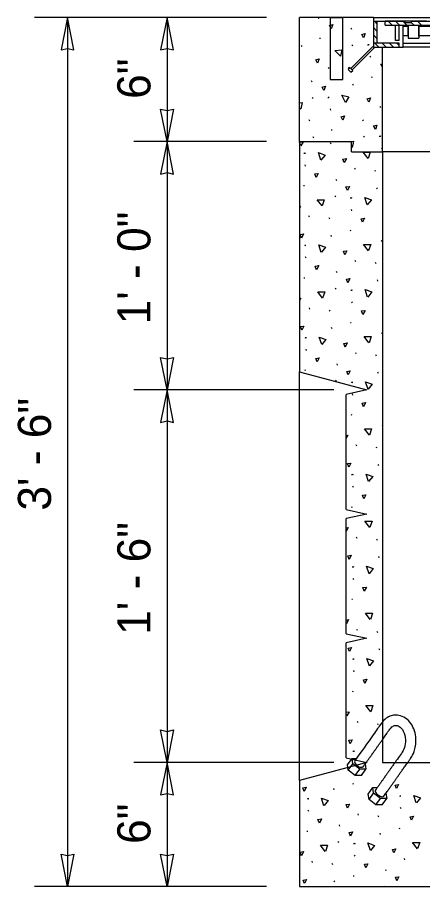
# Model space of a CAD drawing. Extents: x 99862 to 103151, y 100000 to 105076.
# Drawn here: x 100850.3 to 101045.9, y 100268.1 to 100688.1 of the extents above; entities that cross this region are included whole.
import ezdxf

# ---------------------------------------------------------------- set-up
doc = ezdxf.new("R2010")
doc.units = 0
for name, color, linetype in [('Level 15', 7, 'Continuous'), ('Level 19', 7, 'Continuous'), ('Level 2', 7, 'Continuous'), ('Level 20', 7, 'Continuous'), ('Level 3', 7, 'Continuous'), ('Level 4', 7, 'Continuous'), ('Level 5', 7, 'Continuous'), ('Level 50', 7, 'Continuous'), ('Level 7', 7, 'Continuous')]:
    doc.layers.add(name, color=color, linetype=linetype)

msp = doc.modelspace()

# ---------------------------------------------------------------- linework, layer by layer
at = {"layer": 'Level 15'}
for p, q in [((100970.51, 100688.11), (100858.51, 100688.11)), ((100874.51, 100688.11), (100874.51, 100268.11)), ((100922.51, 100688.11), (100922.51, 100628.11)), ((100970.51, 100628.11), (100906.51, 100628.11)), ((100922.51, 100628.11), (100922.51, 100508.11)), ((101003.01, 100508.11), (100906.51, 100508.11)), ((100922.51, 100508.11), (100922.51, 100328.11)), ((101003.01, 100328.11), (100906.51, 100328.11)), ((100922.51, 100328.11), (100922.51, 100268.11)), ((100970.51, 100268.11), (100858.51, 100268.11))]:
    msp.add_line(p, q, dxfattribs=at)
for points in [[(100874.51, 100688.11), (100871.43, 100672.38), (100874.51, 100673.11), (100877.59, 100672.38)], [(100922.51, 100688.11), (100919.43, 100672.38), (100922.51, 100673.11), (100925.59, 100672.38)], [(100922.51, 100628.11), (100919.43, 100643.83), (100922.51, 100643.1), (100925.59, 100643.83)], [(100922.51, 100628.11), (100919.43, 100612.38), (100922.51, 100613.11), (100925.59, 100612.38)], [(100922.51, 100508.11), (100919.43, 100523.83), (100922.51, 100523.1), (100925.59, 100523.83)], [(100922.51, 100508.11), (100919.43, 100492.38), (100922.51, 100493.11), (100925.59, 100492.38)], [(100922.51, 100328.11), (100919.43, 100343.83), (100922.51, 100343.1), (100925.59, 100343.83)], [(100922.51, 100328.11), (100919.43, 100312.38), (100922.51, 100313.11), (100925.59, 100312.38)], [(100874.51, 100268.11), (100871.43, 100283.83), (100874.51, 100283.1), (100877.59, 100283.83)], [(100922.51, 100268.11), (100919.43, 100283.83), (100922.51, 100283.1), (100925.59, 100283.83)]]:
    msp.add_lwpolyline(points, close=True, dxfattribs=at)
at = {"layer": 'Level 19'}
for p, q in [((100996.03, 100687.5), (100995.71, 100688.07)), ((101011.79, 100682.3), (101011.47, 100682.87)), ((100987.75, 100673.97), (100987.43, 100674.54)), ((100996.17, 100678.05), (100996.65, 100678.03)), ((101011.73, 100674.9), (101012.25, 100674.59)), ((101019.3, 100674.89), (101019.78, 100674.86)), ((101019.58, 100675.01), (101020.06, 100674.98)), ((101020.87, 100668.78), (101020.56, 100669.35)), ((101000.86, 100663.26), (101000.54, 100663.83)), ((101010.68, 100663.45), (101010.36, 100664.02)), ((100992.59, 100656.82), (100992.27, 100657.39)), ((101021.01, 100659.33), (101021.49, 100659.3)), ((101012.6, 100655.25), (101012.28, 100655.82)), ((100992.53, 100649.42), (100993.05, 100649.11)), ((101000.1, 100649.41), (101000.58, 100649.38)), ((101000.38, 100649.53), (101000.86, 100649.5)), ((101025.71, 100644.54), (101025.39, 100645.11)), ((101001.67, 100643.3), (101001.36, 100643.87)), ((100991.48, 100637.97), (100991.16, 100638.54)), ((101017.43, 100638.09), (101017.12, 100638.67)), ((101001.81, 100633.85), (101002.29, 100633.83)), ((100993.4, 100629.77), (100993.08, 100630.34)), ((101017.37, 100630.7), (101017.89, 100630.39)), ((101024.94, 100630.68), (101025.42, 100630.66)), ((101025.23, 100630.81), (101025.7, 100630.78)), ((101001.73, 100626.82), (101001.49, 100627.43)), ((101026.51, 100624.59), (101026.2, 100625.15)), ((100988.61, 100622.55), (100989.08, 100622.46)), ((100988.91, 100622.63), (100989.38, 100622.55)), ((100989.43, 100616.29), (100989.19, 100616.9)), ((101013.44, 100614.59), (101013.19, 100615.2)), ((101023.21, 100613.59), (101022.96, 100614.19)), ((100988.42, 100606.9), (100988.89, 100606.82)), ((101004.44, 100609.21), (101004.2, 100609.81)), ((101024.11, 100605.21), (101023.87, 100605.82)), ((101003.48, 100601.87), (101003.96, 100601.5)), ((101010.99, 100600.94), (101011.46, 100600.85)), ((101011.29, 100601.02), (101011.76, 100600.94)), ((101011.81, 100594.68), (101011.57, 100595.29)), ((100991.28, 100591.64), (100991.03, 100592.25)), ((101001.04, 100590.64), (101000.8, 100591.24)), ((101001.95, 100582.26), (101001.7, 100582.87)), ((101010.8, 100585.29), (101011.27, 100585.2)), ((100988.83, 100577.99), (100989.3, 100577.9)), ((100989.12, 100578.07), (100989.6, 100577.99)), ((101025.86, 100580.26), (101026.34, 100579.89)), ((100989.65, 100571.73), (100989.41, 100572.34)), ((101013.66, 100570.03), (101013.41, 100570.64)), ((101023.42, 100569.02), (101023.18, 100569.63)), ((101004.66, 100564.65), (101004.41, 100565.25)), ((100988.64, 100562.34), (100989.11, 100562.25)), ((101024.33, 100560.65), (101024.08, 100561.26)), ((101003.7, 100557.31), (101004.17, 100556.94)), ((101011.5, 100556.46), (101011.98, 100556.38)), ((101011.21, 100556.38), (101011.68, 100556.29)), ((101012.03, 100550.12), (101011.78, 100550.73)), ((100991.49, 100547.08), (100991.25, 100547.69)), ((101001.26, 100546.08), (101001.02, 100546.68)), ((101011.02, 100540.73), (101011.49, 100540.64)), ((101002.17, 100537.7), (101001.92, 100538.31)), ((101026.08, 100535.7), (101026.51, 100535.36)), ((100989.05, 100533.43), (100989.52, 100533.34)), ((100989.34, 100533.51), (100989.81, 100533.43)), ((100989.87, 100527.17), (100989.62, 100527.78)), ((101013.87, 100525.47), (101013.63, 100526.08)), ((101023.64, 100524.46), (101023.4, 100525.07)), ((101004.88, 100520.09), (101004.63, 100520.69)), ((100988.86, 100517.78), (100989.33, 100517.69)), ((101024.55, 100516.09), (101024.3, 100516.7)), ((101003.92, 100512.75), (101004.39, 100512.38)), ((101011.43, 100511.82), (101011.9, 100511.73)), ((101011.72, 100511.9), (101012.19, 100511.82)), ((101012.25, 100505.56), (101012, 100506.17)), ((101011.23, 100496.17), (101011.71, 100496.08)), ((101026.29, 100491.14), (101026.51, 100490.97)), ((101014.09, 100480.91), (101013.85, 100481.52)), ((101023.86, 100479.9), (101023.61, 100480.51)), ((101024.76, 100471.53), (101024.52, 100472.14)), ((101011.64, 100467.25), (101012.12, 100467.17)), ((101011.94, 100467.34), (101012.41, 100467.25)), ((101012.47, 100461), (101012.22, 100461.61)), ((101011.45, 100451.61), (101011.93, 100451.52)), ((101014.31, 100436.35), (101014.06, 100436.96)), ((101024.08, 100435.34), (101023.83, 100435.95)), ((101024.98, 100426.97), (101024.74, 100427.58)), ((101011.86, 100422.69), (101012.34, 100422.61)), ((101012.16, 100422.78), (101012.63, 100422.69)), ((101012.68, 100416.44), (101012.44, 100417.05)), ((101011.67, 100407.05), (101012.14, 100406.96)), ((101014.53, 100391.79), (101014.28, 100392.4)), ((101024.29, 100390.78), (101024.05, 100391.39)), ((101025.2, 100382.41), (101024.95, 100383.02)), ((101012.08, 100378.13), (101012.55, 100378.05)), ((101012.37, 100378.22), (101012.85, 100378.13)), ((101012.9, 100371.88), (101012.66, 100372.48)), ((101011.89, 100362.49), (101012.36, 100362.4)), ((101014.74, 100347.23), (101014.5, 100347.84)), ((101024.51, 100346.22), (101024.27, 100346.83)), ((101012.3, 100333.57), (101012.77, 100333.49)), ((101012.59, 100333.66), (101013.06, 100333.57)), ((101012.11, 100317.92), (101012.58, 100317.84)), ((101003.26, 100314.9), (101003.01, 100315.51)), ((100990.14, 100310.62), (100990.61, 100310.54)), ((100990.43, 100310.71), (100990.9, 100310.62)), ((101034.68, 100311.96), (101035.15, 100311.87)), ((101034.97, 100312.05), (101035.44, 100311.96)), ((100990.96, 100304.37), (100990.71, 100304.97)), ((101035.5, 100305.7), (101035.25, 100306.31)), ((101014.96, 100302.67), (101014.72, 100303.27)), ((101024.73, 100301.66), (101024.48, 100302.27)), ((101005.97, 100297.28), (101005.72, 100297.89)), ((101034.49, 100296.31), (101034.96, 100296.23)), ((100989.94, 100294.98), (100990.42, 100294.89)), ((101025.64, 100293.29), (101025.39, 100293.89)), ((101005, 100289.95), (101005.48, 100289.58)), ((101012.52, 100289.01), (101012.99, 100288.93)), ((101012.81, 100289.1), (101013.28, 100289.01)), ((100992.8, 100279.72), (100992.55, 100280.33)), ((101002.57, 100278.71), (101002.32, 100279.32)), ((101013.34, 100282.75), (101013.09, 100283.36)), ((101037.34, 100281.05), (101037.1, 100281.66)), ((101028.35, 100275.67), (101028.1, 100276.28)), ((101003.47, 100270.34), (101003.23, 100270.94)), ((101012.32, 100273.36), (101012.8, 100273.28)), ((101027.38, 100268.33), (101027.68, 100268.11))]:
    msp.add_line(p, q, dxfattribs=at)
for points in [[(101001.76, 100682.6), (101000.91, 100684.24), (101002.51, 100684.7), (101001.76, 100682.6)], [(101017.45, 100678.19), (101016.6, 100679.83), (101018.2, 100680.3), (101017.45, 100678.19)], [(101006.29, 100669.32), (101003.57, 100672.03), (101006.97, 100672.45), (101006.31, 100669.38)], [(101026.51, 100671.42), (101026.36, 100671.83), (101026.51, 100671.85)], [(100995.15, 100665.91), (100994.3, 100667.55), (100995.9, 100668.02), (100995.15, 100665.91)], [(101026.51, 100664.06), (101025.76, 100665.52), (101026.51, 100665.73)], [(100998.25, 100652.72), (100997.4, 100654.36), (100999, 100654.82), (100998.25, 100652.72)], [(101008.62, 100646.99), (101006.99, 100650.47), (101010.33, 100649.7), (101008.66, 100647.04)], [(101019.99, 100647.19), (101019.14, 100648.83), (101020.74, 100649.29), (101019.99, 100647.19)], [(100986.51, 100646.81), (100987.77, 100646.97), (100987.11, 100643.9)], [(100987.09, 100643.84), (100986.51, 100644.41)], [(101007.4, 100638.4), (101006.56, 100640.04), (101008.16, 100640.5), (101007.4, 100638.4)], [(101023.1, 100633.99), (101022.25, 100635.63), (101023.85, 100636.09), (101023.1, 100633.99)], [(100987.19, 100626.06), (100986.54, 100627.79), (100988.19, 100628.05), (100987.19, 100626.06)], [(101011.48, 100628.11), (101012.61, 100628.25), (101011.95, 100625.18)], [(101011.93, 100625.11), (101011.51, 100625.54)], [(100996.78, 100619.11), (100995.59, 100622.76), (100998.81, 100621.59), (100996.83, 100619.15)], [(101008.09, 100617.92), (101007.45, 100619.66), (101009.09, 100619.92), (101008.09, 100617.92)], [(101019.56, 100619.94), (101017.19, 100622.97), (101020.62, 100622.97), (101019.59, 100620)], [(100994.52, 100610.73), (100993.88, 100612.46), (100995.52, 100612.72), (100994.52, 100610.73)], [(101009.57, 100604.44), (101008.92, 100606.18), (101010.57, 100606.44), (101009.57, 100604.44)], [(100997.4, 100596.99), (100995.03, 100600.02), (100998.46, 100600.02), (100997.43, 100597.05)], [(101019.16, 100597.49), (101017.97, 100601.15), (101021.19, 100599.98), (101019.21, 100597.54)], [(100986.51, 100596.9), (100986.93, 100596.97), (100986.51, 100596.13)], [(101016.9, 100589.12), (101016.26, 100590.85), (101017.9, 100591.11), (101016.9, 100589.12)], [(100987.4, 100581.5), (100986.76, 100583.23), (100988.4, 100583.49), (100987.4, 100581.5)], [(100997, 100574.55), (100995.8, 100578.2), (100999.03, 100577.03), (100997.04, 100574.59)], [(101019.78, 100575.38), (101017.41, 100578.41), (101020.84, 100578.41), (101019.81, 100575.44)], [(101008.31, 100573.36), (101007.67, 100575.09), (101009.31, 100575.36), (101008.31, 100573.36)], [(100994.74, 100566.17), (100994.1, 100567.9), (100995.74, 100568.16), (100994.74, 100566.17)], [(101009.78, 100559.88), (101009.14, 100561.62), (101010.78, 100561.88), (101009.78, 100559.88)], [(101019.38, 100552.93), (101018.18, 100556.59), (101021.41, 100555.42), (101019.42, 100552.98)], [(100986.51, 100552.31), (100987.15, 100552.41), (100986.51, 100551.14)], [(100997.62, 100552.43), (100995.25, 100555.46), (100998.68, 100555.46), (100997.65, 100552.49)], [(101017.12, 100544.56), (101016.48, 100546.29), (101018.12, 100546.55), (101017.12, 100544.56)], [(100987.62, 100536.93), (100986.98, 100538.67), (100988.62, 100538.93), (100987.62, 100536.93)], [(100997.22, 100529.98), (100996.02, 100533.64), (100999.24, 100532.47), (100997.26, 100530.03)], [(101020, 100530.82), (101017.63, 100533.84), (101021.06, 100533.85), (101020.03, 100530.88)], [(101008.53, 100528.8), (101007.88, 100530.53), (101009.53, 100530.8), (101008.53, 100528.8)], [(100994.96, 100521.61), (100994.32, 100523.34), (100995.96, 100523.6), (100994.96, 100521.61)], [(101010, 100515.32), (101009.36, 100517.05), (101011, 100517.32), (101010, 100515.32)], [(101019.6, 100508.37), (101018.4, 100512.03), (101021.62, 100510.86), (101019.64, 100508.42)], [(101017.34, 100500), (101016.7, 100501.73), (101018.34, 100501.99), (101017.34, 100500)], [(101020.22, 100486.26), (101017.84, 100489.28), (101021.27, 100489.29), (101020.24, 100486.32)], [(101009.01, 100486.12), (101009.74, 100486.24), (101009.01, 100484.77)], [(101010.22, 100470.76), (101009.58, 100472.49), (101011.22, 100472.76), (101010.22, 100470.76)], [(101019.81, 100463.81), (101018.62, 100467.46), (101021.84, 100466.3), (101019.86, 100463.86)], [(101017.56, 100455.43), (101016.91, 100457.17), (101018.56, 100457.43), (101017.56, 100455.43)], [(101020.43, 100441.7), (101018.06, 100444.72), (101021.49, 100444.73), (101020.46, 100441.76)], [(101009.01, 100441.52), (101009.96, 100441.68), (101009.01, 100439.78)], [(101010.44, 100426.2), (101009.79, 100427.93), (101011.44, 100428.2), (101010.44, 100426.2)], [(101020.03, 100419.25), (101018.84, 100422.9), (101022.06, 100421.74), (101020.08, 100419.3)], [(101017.77, 100410.87), (101017.13, 100412.61), (101018.78, 100412.87), (101017.77, 100410.87)], [(101009.01, 100396.93), (101010.18, 100397.12), (101009.18, 100395.12)], [(101020.65, 100397.14), (101018.28, 100400.16), (101021.71, 100400.17), (101020.68, 100397.2)], [(101009.18, 100395.12), (101009.01, 100395.57)], [(101010.65, 100381.64), (101010.01, 100383.37), (101011.65, 100383.64), (101010.65, 100381.64)], [(101020.25, 100374.69), (101019.05, 100378.34), (101022.28, 100377.18), (101020.29, 100374.74)], [(101017.99, 100366.31), (101017.35, 100368.04), (101018.99, 100368.31), (101017.99, 100366.31)], [(101020.87, 100352.58), (101018.5, 100355.6), (101021.93, 100355.61), (101020.9, 100352.64)], [(101009.01, 100352.33), (101010.4, 100352.55), (101009.4, 100350.56)], [(101009.4, 100350.56), (101009.01, 100351.6)], [(101010.87, 100337.08), (101010.23, 100338.81), (101011.87, 100339.08), (101010.87, 100337.08)], [(101033.25, 100315.47), (101032.61, 100317.2), (101034.25, 100317.46), (101033.25, 100315.47)], [(100988.71, 100314.13), (100988.07, 100315.86), (100989.71, 100316.13), (100988.71, 100314.13)], [(100998.3, 100307.18), (100997.11, 100310.83), (101000.33, 100309.67), (100998.35, 100307.23)], [(101042.85, 100308.52), (101041.65, 100312.17), (101044.87, 100311), (101042.89, 100308.57)], [(101009.61, 100306), (101008.97, 100307.73), (101010.62, 100307.99), (101009.61, 100306)], [(100996.05, 100298.8), (100995.4, 100300.53), (100997.05, 100300.8), (100996.05, 100298.8)], [(101040.59, 100300.14), (101039.95, 100301.87), (101041.59, 100302.14), (101040.59, 100300.14)], [(101011.09, 100292.52), (101010.45, 100294.25), (101012.09, 100294.52), (101011.09, 100292.52)], [(100998.92, 100285.07), (100996.55, 100288.09), (100999.98, 100288.1), (100998.95, 100285.13)], [(101020.68, 100285.57), (101019.49, 100289.22), (101022.71, 100288.05), (101020.73, 100285.62)], [(101043.47, 100286.4), (101041.09, 100289.43), (101044.52, 100289.43), (101043.49, 100286.47)], [(100987.45, 100283.05), (100986.81, 100284.78), (100988.45, 100285.04), (100987.45, 100283.05)], [(101031.99, 100284.39), (101031.35, 100286.12), (101032.99, 100286.38), (101031.99, 100284.39)], [(101018.43, 100277.19), (101017.78, 100278.92), (101019.43, 100279.19), (101018.43, 100277.19)], [(100988.93, 100269.57), (100988.28, 100271.3), (100989.93, 100271.57), (100988.93, 100269.57)], [(101033.47, 100270.91), (101032.83, 100272.64), (101034.47, 100272.9), (101033.47, 100270.91)]]:
    msp.add_lwpolyline(points, dxfattribs=at)
at = {"layer": 'Level 2'}
for p, q in [((100986.51, 100628.11), (100986.51, 100516.82)), ((100986.51, 100628.11), (101011.51, 100628.11)), ((101011.51, 100623.11), (101011.51, 100628.11)), ((101011.51, 100623.11), (101026.51, 100623.11)), ((101026.51, 100623.11), (101026.51, 100328.11)), ((100986.51, 100516.82), (101019.01, 100508.11)), ((100986.51, 100319.4), (100986.51, 100516.82)), ((101019.01, 100508.11), (101009.01, 100505.92)), ((101009.01, 100450.3), (101009.01, 100505.92)), ((101009.01, 100450.3), (101019.01, 100448.11)), ((101019.01, 100448.11), (101009.01, 100445.92)), ((101009.01, 100390.3), (101009.01, 100445.92)), ((101009.01, 100390.3), (101019.01, 100388.11)), ((101019.01, 100388.11), (101009.01, 100385.92)), ((101009.01, 100330.3), (101009.01, 100385.92)), ((101009.01, 100330.3), (101019.01, 100328.11)), ((101019.01, 100328.11), (100986.51, 100319.4)), ((101026.51, 100328.11), (101176.51, 100328.11)), ((100986.51, 100319.4), (100986.51, 100268.11)), ((100986.51, 100268.11), (101196.51, 100268.11))]:
    msp.add_line(p, q, dxfattribs=at)
at = {"layer": 'Level 3'}
for p, q in [((101022.14, 100688.11), (100986.51, 100688.11)), ((100986.51, 100628.11), (100986.51, 100688.11)), ((101022.14, 100688.11), (101022.14, 100686.23)), ((101022.14, 100688.11), (101390.89, 100688.11)), ((101024.01, 100675.61), (101022.14, 100675.61)), ((101026.51, 100623.11), (101026.51, 100673.73)), ((101386.51, 100623.11), (101026.51, 100623.11))]:
    msp.add_line(p, q, dxfattribs=at)
at = {"layer": 'Level 4'}
for p, q in [((101022.14, 100686.23), (101022.14, 100673.73)), ((101022.14, 100686.23), (101024.01, 100686.23)), ((101022.14, 100683.18), (101024.01, 100681.3)), ((101022.61, 100686.23), (101024.01, 100684.84)), ((101024.01, 100675.61), (101024.01, 100686.23)), ((101022.14, 100679.64), (101024.01, 100677.77)), ((101022.14, 100676.11), (101022.63, 100675.61)), ((101022.9, 100675.61), (101024.78, 100673.73)), ((101034.64, 100675.61), (101024.01, 100675.61)), ((101026.44, 100675.61), (101028.31, 100673.73)), ((101029.97, 100675.61), (101031.85, 100673.73)), ((101033.51, 100675.61), (101034.64, 100674.48)), ((101034.64, 100673.73), (101034.64, 100675.61)), ((101036.51, 100675.61), (101067.76, 100675.61)), ((101022.14, 100673.73), (101034.64, 100673.73)), ((101067.76, 100673.73), (101036.51, 100673.73))]:
    msp.add_line(p, q, dxfattribs=at)
at = {"layer": 'Level 5'}
for p, q in [((101024.01, 100686.23), (101027.76, 100686.23)), ((101027.76, 100686.23), (101037.49, 100686.23)), ((101027.76, 100684.36), (101027.76, 100686.23)), ((101027.76, 100684.36), (101389.01, 100684.36)), ((101029.29, 100686.23), (101031.16, 100684.36)), ((101032.76, 100676.86), (101032.76, 100684.36)), ((101032.82, 100686.23), (101034.7, 100684.36)), ((101034.64, 100676.86), (101034.64, 100684.36)), ((101036.36, 100686.23), (101038.23, 100684.36)), ((101036.51, 100673.73), (101036.51, 100684.36)), ((101039.01, 100683.73), (101036.51, 100683.73)), ((101038.97, 100686.23), (101037.49, 100686.23)), ((101037.49, 100685.61), (101037.49, 100686.23)), ((101037.49, 100685.61), (101040.46, 100685.61)), ((101040.46, 100686.23), (101038.97, 100686.23)), ((101039.01, 100684.36), (101039.01, 100678.11)), ((101040.46, 100686.23), (101057.49, 100686.23)), ((101040.46, 100686.23), (101040.46, 100685.61)), ((101040.46, 100685.67), (101041.77, 100684.36)), ((101043.43, 100686.23), (101045.3, 100684.36)), ((101044.01, 100684.36), (101044.01, 100678.11)), ((101058.39, 100683.73), (101044.01, 100683.73)), ((101036.51, 100679.36), (101039.01, 100679.36)), ((101044.01, 100679.36), (101058.39, 100679.36)), ((101034.64, 100676.86), (101032.76, 100676.86)), ((101039.01, 100678.11), (101044.01, 100678.11)), ((101034.64, 100673.73), (101036.51, 100673.73))]:
    msp.add_line(p, q, dxfattribs=at)
at = {"layer": 'Level 50'}
for p, q in [((101001.2, 100688.11), (101001.2, 100658.11)), ((101001.2, 100688.11), (101007.45, 100688.11)), ((101007.45, 100658.11), (101007.45, 100688.11)), ((101031.35, 100686.23), (101027.76, 100686.23)), ((101027.76, 100686.23), (101028.97, 100686.23)), ((101028.97, 100686.23), (101037.49, 100686.23)), ((101030.22, 100686.23), (101028.97, 100686.23)), ((101037.49, 100686.23), (101030.22, 100686.23)), ((101036.51, 100686.23), (101033.85, 100686.23)), ((101043.47, 100686.23), (101036.51, 100686.23)), ((101036.51, 100679.05), (101036.51, 100684.05)), ((101039.01, 100679.05), (101039.01, 100684.05)), ((101047.72, 100686.23), (101040.46, 100686.23)), ((101040.46, 100686.23), (101048.97, 100686.23)), ((101044.01, 100679.05), (101044.01, 100684.05)), ((101021.8, 100674.06), (101011.2, 100663.46)), ((101021.8, 100674.06), (101022.47, 100673.4)), ((101011.86, 100662.79), (101022.47, 100673.4)), ((101010.87, 100663.79), (101009.98, 100662.91)), ((101009.98, 100662.91), (101011.31, 100661.58)), ((101012.19, 100662.46), (101010.87, 100663.79)), ((101011.31, 100661.58), (101012.19, 100662.46)), ((101001.2, 100658.11), (101007.45, 100658.11)), ((101009.69, 100326.98), (101011.88, 100330.08)), ((101012.21, 100327.48), (101011.88, 100330.08)), ((101011.88, 100330.08), (101013.99, 100330.08)), ((101010.03, 100324.38), (101009.69, 100326.98)), ((101010.03, 100324.38), (101012.21, 100327.48)), ((101015.56, 100324.87), (101012.21, 100327.48)), ((101018.22, 100327.48), (101018.56, 100324.87)), ((101013.37, 100321.78), (101010.03, 100324.38)), ((101013.37, 100321.78), (101015.56, 100324.87)), ((101016.37, 100321.78), (101013.37, 100321.78)), ((101018.56, 100324.87), (101015.56, 100324.87)), ((101016.37, 100321.78), (101018.56, 100324.87)), ((101019.69, 100312.84), (101021.88, 100315.94)), ((101020.03, 100310.24), (101019.69, 100312.84)), ((101020.03, 100310.24), (101022.21, 100313.33)), ((101022.21, 100313.33), (101021.88, 100315.94)), ((101021.88, 100315.94), (101024, 100315.94)), ((101025.56, 100310.73), (101022.21, 100313.33)), ((101028.22, 100313.33), (101028.56, 100310.73)), ((101023.37, 100307.64), (101020.03, 100310.24)), ((101023.37, 100307.64), (101025.56, 100310.73)), ((101028.56, 100310.73), (101025.56, 100310.73)), ((101026.37, 100307.64), (101028.56, 100310.73)), ((101026.37, 100307.64), (101023.37, 100307.64))]:
    msp.add_line(p, q, dxfattribs=at)
for centre, start_param, end_param in [((101015.22, 100327.48), 6.283171, 7.762101), ((101015.22, 100327.48), 1.478915, 3.146648), ((101025.22, 100313.33), 6.277491, 6.714903), ((101025.22, 100313.33), 0.431718, 2.526113), ((101025.22, 100313.33), 2.526113, 3.141578)]:
    msp.add_ellipse(centre, major_axis=(-2.04, 1.44), ratio=0.5, start_param=start_param, end_param=end_param, dxfattribs=at)
for points, degree in [([(101026.51, 100347.67), (101026.34, 100347.46), (101025.46, 100346.37), (101021.1, 100340), (101016.78, 100334.09), (101013.18, 100328.92)], 3), ([(101017.26, 100326.03), (101020.33, 100330.42), (101023.44, 100334.74), (101026.51, 100339.1)], 2), ([(101032.59, 100328.11), (101029.45, 100323.69), (101026.32, 100319.18), (101023.18, 100314.78)], 2), ([(101027.26, 100311.89), (101031.09, 100317.3), (101034.89, 100322.69), (101038.73, 100328.11)], 2)]:
    msp.add_open_spline(points, degree=degree, dxfattribs=at)
at = {"layer": 'Level 7'}
for points in [[(101033.03, 100351.02), (101032.65, 100351.04), (101031.37, 100350.89), (101028.88, 100350.15), (101027.27, 100348.57), (101026.51, 100347.67)], [(101038.73, 100328.11), (101039.09, 100328.62), (101039.58, 100329.3), (101040.61, 100330.76), (101042.3, 100333.97), (101043.24, 100341.4), (101039.64, 100349.17), (101034.87, 100351.01), (101033.03, 100351.02)], [(101026.51, 100339.1), (101028.71, 100342.24), (101029.22, 100342.98), (101030.31, 100344.56), (101031.84, 100346), (101033.49, 100346.18), (101035.68, 100345), (101037.6, 100341.49), (101037.71, 100336.75), (101036.65, 100333.75), (101034.73, 100331.11), (101033.49, 100329.38), (101032.59, 100328.11)]]:
    msp.add_open_spline(points, degree=3, dxfattribs=at)

# ---------------------------------------------------------------- texts
at = {"layer": 'Level 20'}
for s, p in [('6"', (100914.51, 100648.74)), ('1\' - 0"', (100914.51, 100539.77)), ('3\' - 6"', (100866.51, 100449.77)), ('1\' - 6"', (100914.51, 100389.77)), ('6"', (100914.51, 100288.74))]:
    msp.add_text(s, height=16, rotation=90, dxfattribs=at).set_placement(p)

doc.saveas('drawing.dxf')
